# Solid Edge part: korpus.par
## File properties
Author: Türk
Template: Iso Part.par
Last saved by: Türk
Revision: 16
Application: Solid Edge
Accuracy: 0,990
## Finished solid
Body 1: solid body, 64 faces, 175 edges, 114 vertices.
  Faces by surface: plane 36, cylinder 24, cone 2, spline 2
  Edges by curve: line 91, circle 57, curve on surface 23, ellipse 2, intersection 2
Bounding box of the edges (mm; curved faces can reach further): 217.557 x 635.000 x 221.803, from (-108.7785, -635, -110) to (108.7785, 0, 111.8034).
Cylindrical faces by radius (mm): R22 x4, R27.5 x4, R45 x5, R50 x5, R55 x2, R60 x2, R80 x1, R100 x1
Conical faces (half-angle, radius in mm at the cone's reference point): 45 deg R55 x2
Planar faces by outward normal: +x 4, +y 5, +z 4, -x 4, -y 4, -z 2, oblique 13
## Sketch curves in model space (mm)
circle centre (0, 0, 0) radius 123.6068
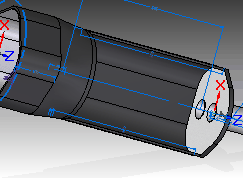
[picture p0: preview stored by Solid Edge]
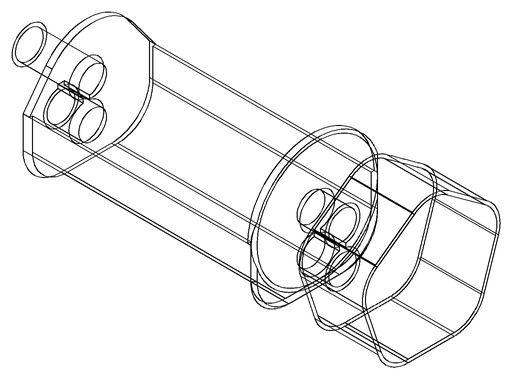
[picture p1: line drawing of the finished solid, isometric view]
